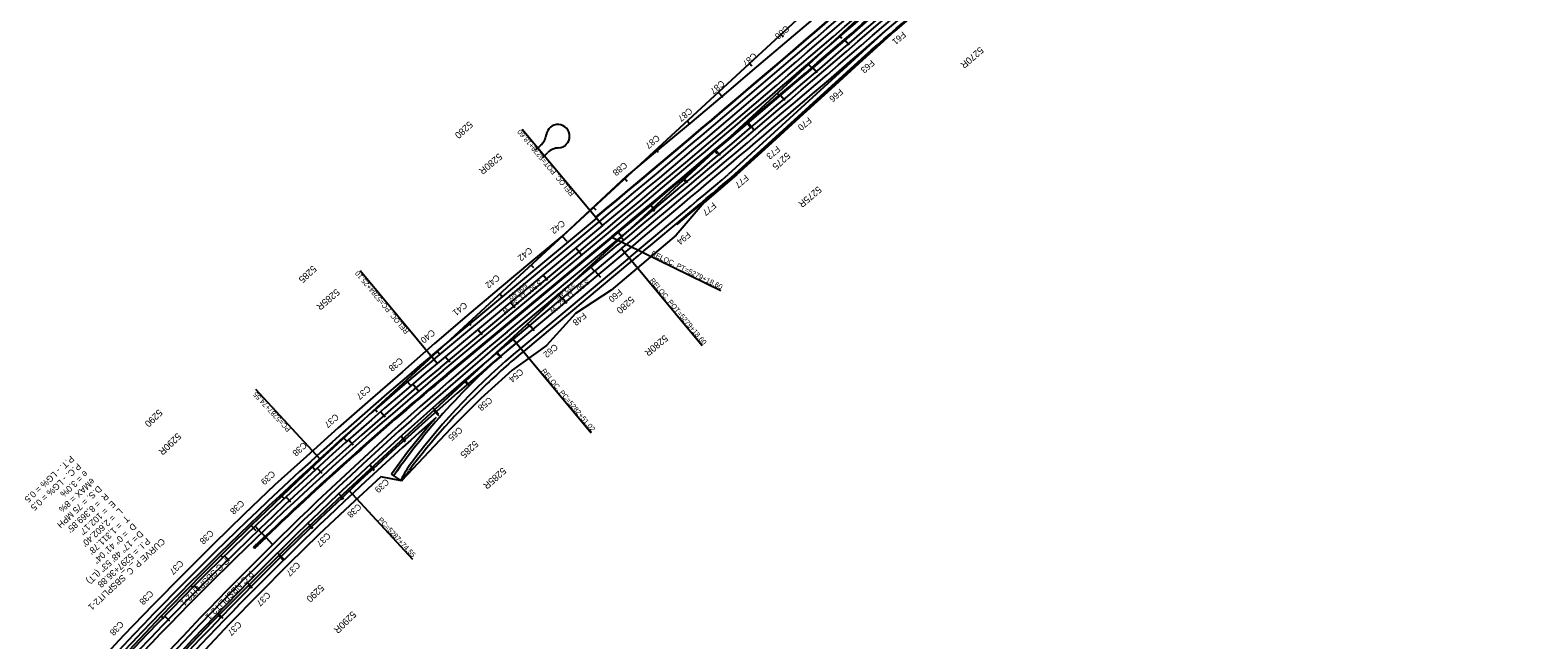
# Model space of a CAD drawing. Extents: x 2160877 to 2175861, y 601747 to 617724.
# Drawn here: x 2162989 to 2166538, y 605470 to 606904 of the extents above; entities that cross this region are included whole.
import ezdxf

# ---------------------------------------------------------------- set-up
doc = ezdxf.new("R2010")
doc.units = 0
for name, color, linetype in [('RD_HC_Cl', 7, 'Continuous'), ('RD_HC_CL_Rel', 7, 'Continuous'), ('RD_HC_Data', 7, 'Continuous'), ('RD_HC_Data_Rel', 7, 'Continuous'), ('RD_HC_Data_Tic', 7, 'Continuous'), ('RD_HC_Data_Tic_Rel', 7, 'Continuous'), ('RD_HC_TX_Rel_Sta50', 7, 'Continuous'), ('RD_HC_TX_Rel_StaOther', 7, 'Continuous'), ('RD_HC_TX_StaOther', 7, 'Continuous'), ('RD_PD_CstnLmt', 7, 'Continuous'), ('RD_PD_CstnLmt_TX', 7, 'Continuous'), ('RD_PD_Final_LnLine', 7, 'Continuous'), ('RD_PD_Final_TrvlWay', 7, 'Continuous'), ('RD_PD_GR', 7, 'Continuous'), ('RD_PD_MedBWall', 7, 'Continuous')]:
    doc.layers.add(name, color=color, linetype=linetype)

msp = doc.modelspace()

# ---------------------------------------------------------------- linework, layer by layer
at = {"layer": 'RD_HC_Cl'}
for p, q in [((2172207.3, 613775.1), (2163672.2, 605893.8)), ((2172272.5, 613704.6), (2163737.4, 605823.3))]:
    msp.add_line(p, q, dxfattribs=at)
for radius in [8641.9, 8545.9]:
    msp.add_arc((2169535, 599544.7), radius, 132.71947, 164.41949, dxfattribs=at)
at = {"layer": 'RD_HC_CL_Rel'}
for p, q in [((2164335.8, 606444.4), (2163946.7, 606120.1)), ((2164380.9, 606390.4), (2164125.5, 606177.5))]:
    msp.add_line(p, q, dxfattribs=at)
for centre, radius, start, end in [((2135996.9, 640448.5), 44300, 309.80773, 312.71947), ((2169810, 599356.6), 8879.1, 129.80773, 145.62858), ((2169305.2, 599690.4), 8369.8, 129.80773, 147.62243)]:
    msp.add_arc(centre, radius, start, end, dxfattribs=at)
at = {"layer": 'RD_HC_Data'}
for p, q in [((2163672.2, 605893.8), (2163520.1, 606058.6)), ((2163737.4, 605823.3), (2163888.4, 605659.7))]:
    msp.add_line(p, q, dxfattribs=at)
at = {"layer": 'RD_HC_Data_Rel'}
for p, q in [((2164335.8, 606444.4), (2164147.1, 606670.9)), ((2164358.3, 606417.4), (2164614.3, 606291.9)), ((2164380.9, 606390.4), (2164570.9, 606162.4)), ((2163946.7, 606120.1), (2163765.3, 606337.8)), ((2164125.5, 606177.5), (2164309.7, 605956.5))]:
    msp.add_line(p, q, dxfattribs=at)
at = {"layer": 'RD_HC_Data_Tic'}
for p, q in [((2164755.6, 606894.2), (2164761, 606888.3)), ((2164894.2, 606891.5), (2164899.6, 606885.6)), ((2164682.1, 606826.3), (2164687.5, 606820.5)), ((2164820.7, 606823.6), (2164826.1, 606817.8)), ((2164608.6, 606758.5), (2164619.5, 606746.7)), ((2164747.2, 606755.8), (2164752.7, 606749.9)), ((2164535.2, 606690.6), (2164540.6, 606684.8)), ((2164673.8, 606688), (2164684.6, 606676.2)), ((2164461.7, 606622.8), (2164467.1, 606616.9)), ((2164600.3, 606620.1), (2164605.7, 606614.2)), ((2164388.2, 606555), (2164393.7, 606549.1)), ((2164526.8, 606552.3), (2164532.3, 606546.4)), ((2164314.8, 606487.1), (2164320.2, 606481.2)), ((2164453.4, 606484.4), (2164458.8, 606478.6)), ((2164241.3, 606419.3), (2164252.1, 606407.5)), ((2164379.9, 606416.6), (2164385.3, 606410.7)), ((2164167.8, 606351.4), (2164173.3, 606345.6)), ((2164306.4, 606348.8), (2164317.3, 606337)), ((2164094.4, 606283.6), (2164099.8, 606277.7)), ((2164233, 606280.9), (2164238.4, 606275)), ((2164020.9, 606215.8), (2164026.3, 606209.9)), ((2164159.5, 606213.1), (2164164.9, 606207.2)), ((2163947.4, 606147.9), (2163952.8, 606142)), ((2164086, 606145.2), (2164091.4, 606139.4)), ((2163873.9, 606080.1), (2163884.8, 606068.3)), ((2164012.5, 606077.4), (2164018, 606071.5)), ((2163800.5, 606012.2), (2163805.9, 606006.4)), ((2163939.1, 606009.5), (2163949.9, 605997.8)), ((2163727, 605944.4), (2163732.4, 605938.5)), ((2163865.6, 605941.7), (2163871, 605935.8)), ((2163653.6, 605876.5), (2163659, 605870.7)), ((2163792.1, 605873.9), (2163797.6, 605868)), ((2163580.7, 605808), (2163586.2, 605802.3)), ((2163718.7, 605806), (2163724.1, 605800.1)), ((2163508.6, 605738.7), (2163519.8, 605727.3)), ((2163645.8, 605737.5), (2163651.3, 605731.7)), ((2163437.4, 605668.6), (2163443, 605662.9)), ((2163573.8, 605668.2), (2163584.9, 605656.7)), ((2163366.9, 605597.6), (2163372.6, 605592)), ((2163502.5, 605598), (2163508.2, 605592.3)), ((2163297.3, 605525.8), (2163303, 605520.3)), ((2163432.1, 605527), (2163437.8, 605521.4))]:
    msp.add_line(p, q, dxfattribs=at)
at = {"layer": 'RD_HC_Data_Tic_Rel'}
for p, q in [((2164906.6, 606881.9), (2164917.1, 606869.8)), ((2164830.8, 606816.7), (2164841.2, 606804.6)), ((2164754.8, 606751.7), (2164765.2, 606739.5)), ((2164678.6, 606686.9), (2164691.6, 606671.6)), ((2164602.4, 606622.2), (2164612.7, 606610)), ((2164525.9, 606557.7), (2164536.2, 606545.5)), ((2164449.3, 606493.4), (2164459.6, 606481.2)), ((2164372.6, 606429.3), (2164382.9, 606417)), ((2164273.3, 606392.3), (2164286.1, 606376.9)), ((2164196.5, 606328.3), (2164206.7, 606316)), ((2164318.3, 606338.2), (2164331.1, 606322.9)), ((2164119.7, 606264.2), (2164129.9, 606251.9)), ((2164241.5, 606274.2), (2164251.7, 606261.9)), ((2164042.8, 606200.2), (2164053.1, 606187.9)), ((2164164.7, 606210.2), (2164174.9, 606197.9)), ((2164087.9, 606146.1), (2164098.3, 606133.8)), ((2163966, 606136.2), (2163976.3, 606123.9)), ((2164011.8, 606081.2), (2164022.3, 606069.1)), ((2163889.4, 606071.9), (2163902.4, 606056.7)), ((2163813.6, 606006.8), (2163824.1, 605994.7)), ((2163936.5, 606015.5), (2163949.7, 606000.5)), ((2163738.5, 605940.7), (2163749.1, 605928.7)), ((2163861.9, 605948.9), (2163872.6, 605937)), ((2163664.2, 605873.7), (2163675, 605861.9)), ((2163788, 605881.5), (2163798.8, 605869.7)), ((2163590.7, 605805.9), (2163601.7, 605794.2)), ((2163714.9, 605813.3), (2163725.9, 605801.6)), ((2163518.1, 605737.2), (2163531.9, 605722.7)), ((2163642.6, 605744.2), (2163653.7, 605732.7)), ((2163446.2, 605667.6), (2163457.4, 605656.2)), ((2163571, 605674.4), (2163585.1, 605660.1)), ((2163375.3, 605597.2), (2163386.6, 605585.9)), ((2163500.3, 605603.7), (2163511.6, 605592.4)), ((2163305.1, 605525.9), (2163316.6, 605514.8)), ((2163430.3, 605532.2), (2163441.8, 605521.1))]:
    msp.add_line(p, q, dxfattribs=at)
at = {"layer": 'RD_PD_CstnLmt'}
for p, q in [((2165098, 606966.6), (2165022.3, 606901)), ((2164851.1, 606946.4), (2164774.7, 606882.1)), ((2165022.3, 606901), (2164948, 606833.8)), ((2164774.7, 606882.1), (2164698.2, 606818)), ((2164948, 606833.8), (2164874, 606766.3)), ((2164698.2, 606818), (2164622.4, 606753.1)), ((2164622.4, 606753.1), (2164546.3, 606688.5)), ((2164874, 606766.3), (2164800, 606698.8)), ((2164546.3, 606688.5), (2164469.6, 606624.7)), ((2164800, 606698.8), (2164725.9, 606631.3)), ((2164469.6, 606624.7), (2164392.9, 606560.8)), ((2164725.9, 606631.3), (2164651.8, 606563.7)), ((2164392.9, 606560.8), (2164246.7, 606424.2)), ((2164651.8, 606563.7), (2164575.6, 606498.7)), ((2164575.6, 606498.7), (2164509.5, 606421.7)), ((2164246.7, 606424.2), (2164169.6, 606360.5)), ((2164509.5, 606421.7), (2164356.5, 606292.4)), ((2164169.6, 606360.5), (2164093, 606296.2)), ((2164418.9, 606344.8), (2164418.9, 606344.8)), ((2164093, 606296.2), (2164016.5, 606231.8)), ((2164356.5, 606292.4), (2164272.2, 606237.3)), ((2164016.5, 606231.8), (2163940.4, 606166.9)), ((2164272.2, 606237.3), (2164204.3, 606162.7)), ((2163940.4, 606166.9), (2163865.1, 606100.5)), ((2164204.3, 606162.7), (2164123, 606104.5)), ((2163865.1, 606100.5), (2163789.3, 606034.7)), ((2164123, 606104.5), (2164049.6, 606037.4)), ((2164049.6, 606037.4), (2163979.3, 605966.9)), ((2163789.3, 606034.7), (2163713.9, 605968.3)), ((2163713.9, 605968.3), (2163638.9, 605901.5)), ((2163979.3, 605966.9), (2163862.6, 605843.8)), ((2163638.9, 605901.5), (2163564.3, 605834.1)), ((2163564.3, 605834.1), (2163491.7, 605764.8)), ((2163814.2, 605853.1), (2163741, 605785.6)), ((2163862.6, 605843.8), (2163814.2, 605853.1)), ((2163491.7, 605764.8), (2163419.9, 605694.5)), ((2163741, 605785.6), (2163668.5, 605717.3)), ((2163419.9, 605694.5), (2163348.9, 605623.5)), ((2163668.5, 605717.3), (2163596.9, 605648.2)), ((2163596.9, 605648.2), (2163526.8, 605577.4)), ((2163348.9, 605623.5), (2163278.1, 605552.2)), ((2163526.8, 605577.4), (2163457.1, 605506.3)), ((2163278.1, 605552.2), (2163208.3, 605480)), ((2163457.1, 605506.3), (2163388.7, 605434)), ((2163208.3, 605480), (2163139.9, 605406.4))]:
    msp.add_line(p, q, dxfattribs=at)
at = {"layer": 'RD_PD_Final_LnLine'}
for p, q in [((2165001.8, 606901.7), (2164631.9, 606564.5)), ((2163939.1, 606129.3), (2164328.1, 606453.6)), ((2163954.4, 606110.9), (2164343.5, 606435.2)), ((2163968.5, 606094), (2164357.6, 606418.3)), ((2163970, 606092.2), (2164359.1, 606416.5)), ((2164117.8, 606186.8), (2164373.2, 606399.6)), ((2164388.5, 606381.1), (2164133.2, 606168.3)), ((2164398.8, 606368.9), (2164143.4, 606156)), ((2163862.6, 605843.8), (2163839.6, 605859.9)), ((2163861.2, 605844.7), (2163861.9, 605846.1)), ((2163543.1, 605711), (2163533.3, 605721.3)), ((2163543.1, 605711), (2163559.5, 605693.9))]:
    msp.add_line(p, q, dxfattribs=at)
for centre, radius, start, end in [((2135996.9, 640448.5), 44252.8, 309.80773, 312.71947), ((2135996.9, 640448.5), 44264.8, 309.80773, 312.71947), ((2135996.9, 640448.5), 44276.8, 309.80773, 312.71947), ((2135996.9, 640448.5), 44298.8, 309.80773, 312.71947), ((2135996.9, 640448.5), 44301.2, 309.80773, 312.71947), ((2135996.9, 640448.5), 44323.2, 309.80773, 312.71947), ((2135996.9, 640448.5), 44335.2, 309.80773, 312.71947), ((2135996.9, 640448.5), 44347.2, 310.84704, 312.71947), ((2135996.9, 640448.5), 44239.7, 309.80773, 311.15408), ((2135996.9, 640448.5), 44240.8, 309.80773, 311.15408), ((2135996.9, 640448.5), 44347.2, 309.80773, 310.84704), ((2135996.9, 640448.5), 44363.2, 309.80773, 310.20085), ((2169810, 599356.6), 8891.1, 129.80773, 145.62858), ((2169810, 599356.6), 8867.1, 129.80773, 144.89859), ((2165149.7, 604937.9), 1596, 129.5633, 144.8644), ((2165161.7, 604927.1), 1596, 129.6453, 143.0585), ((2169305.2, 599690.4), 8357.8, 129.80773, 147.62243), ((2169305.2, 599690.4), 8381.8, 129.80773, 136.90521), ((2169327, 599664.3), 8369.8, 129.80773, 133.72726), ((2169327, 599664.3), 8367.5, 129.80773, 133.72726), ((2164070.6, 605747.6), 230.8, 143.0585, 154.736)]:
    msp.add_arc(centre, radius, start, end, dxfattribs=at)
at = {"layer": 'RD_PD_Final_TrvlWay'}
for p, q in [((2164954.1, 606844.7), (2164638.5, 606557)), ((2164954.8, 606843.8), (2164639.3, 606556.2)), ((2164178, 606621.8), (2164191.1, 606633.9)), ((2164194.4, 606604.9), (2164207.2, 606616.7)), ((2163932.7, 606137), (2164321.7, 606461.3)), ((2164321.7, 606461.3), (2164320.5, 606462.8)), ((2163960.8, 606103.2), (2164349.9, 606427.5)), ((2164111.4, 606194.4), (2164366.8, 606407.3)), ((2164405.2, 606361.2), (2164149.8, 606148.4)), ((2163862.6, 605843.8), (2163880.5, 605867.8))]:
    msp.add_line(p, q, dxfattribs=at)
for centre, radius, start, end in [((2135996.9, 640448.5), 44286.8, 309.80773, 311.17861), ((2135996.9, 640448.5), 44313.2, 309.80773, 311.17861), ((2136000.8, 640444), 44353.2, 310.7522, 311.15415), ((2136000.8, 640444), 44354.3, 310.75222, 311.15415), ((2164231, 606654.8), 27.5, 272.8804, 172.6984), ((2164164, 606663.3), 40, 312.7195, 352.6984), ((2164234.4, 606587.3), 40, 92.8804, 132.7195), ((2135996.9, 640448.5), 44373.2, 309.80773, 310.2011), ((2135996.9, 640448.5), 44374.3, 309.98432, 310.20112), ((2169810, 599356.6), 8901.1, 129.80773, 142.13894), ((2165161.7, 604927.1), 1586, 129.6453, 134.0776), ((2169305.2, 599690.4), 8391.8, 129.80773, 137.30123), ((2169305.2, 599690.4), 8347.8, 129.80773, 143.57306), ((2165082.4, 604970.4), 1500, 133.0506, 143.2516), ((2169810, 599356.6), 8857.1, 131.47407, 142.45996), ((2165149.7, 604937.9), 1602, 138.8128, 144.8644)]:
    msp.add_arc(centre, radius, start, end, dxfattribs=at)
at = {"layer": 'RD_PD_GR'}
for p, q in [((2163541.1, 605713.2), (2163514.4, 605687.5)), ((2163514.4, 605687.5), (2163514.7, 605687.2)), ((2163514.7, 605687.2), (2163541.4, 605712.8)), ((2163515.4, 605688.6), (2163516.7, 605689.8)), ((2163515.8, 605688.2), (2163517.1, 605689.4)), ((2163517.2, 605686.7), (2163515.8, 605688.2)), ((2163516.9, 605688.3), (2163516, 605689.2)), ((2163517.5, 605688.9), (2163516.3, 605687.7)), ((2163516.3, 605687.7), (2163517.7, 605686.3)), ((2163516.6, 605685.2), (2163543.3, 605710.9)), ((2163516.9, 605684.9), (2163516.6, 605685.2)), ((2163543.6, 605710.5), (2163516.9, 605684.9)), ((2163517.1, 605689.4), (2163518.5, 605688)), ((2163518.5, 605688), (2163517.2, 605686.7)), ((2163518.9, 605687.5), (2163517.5, 605688.9)), ((2163517.7, 605686.3), (2163518.9, 605687.5)), ((2163517.8, 605687.4), (2163518.7, 605686.5)), ((2163518.1, 605685.8), (2163519.3, 605687.1)), ((2163519.3, 605691.6), (2163519, 605691.9)), ((2163521.2, 605694.2), (2163522.4, 605695.4)), ((2163521.2, 605689.6), (2163521.5, 605689.3)), ((2163521.6, 605693.7), (2163522.8, 605694.9)), ((2163523, 605692.3), (2163521.6, 605693.7)), ((2163522.7, 605693.9), (2163521.8, 605694.8)), ((2163523.3, 605694.5), (2163522, 605693.3)), ((2163522, 605693.3), (2163523.4, 605691.8)), ((2163522.8, 605694.9), (2163524.2, 605693.5)), ((2163524.2, 605693.5), (2163523, 605692.3)), ((2163524.7, 605693), (2163523.3, 605694.5)), ((2163523.4, 605691.8), (2163524.7, 605693)), ((2163523.6, 605692.9), (2163524.5, 605692)), ((2163523.8, 605691.4), (2163525.1, 605692.6)), ((2163526.9, 605699.7), (2163528.2, 605700.9)), ((2163527.3, 605699.3), (2163528.6, 605700.5)), ((2163528.7, 605697.8), (2163527.3, 605699.3)), ((2163528.4, 605699.4), (2163527.6, 605700.3)), ((2163529.1, 605700), (2163527.8, 605698.8)), ((2163527.8, 605698.8), (2163529.2, 605697.4)), ((2163528.6, 605700.5), (2163530, 605699.1)), ((2163530, 605699.1), (2163528.7, 605697.8)), ((2163530.5, 605698.6), (2163529.1, 605700)), ((2163529.2, 605697.4), (2163530.5, 605698.6)), ((2163529.4, 605698.4), (2163530.2, 605697.5)), ((2163529.6, 605696.9), (2163530.9, 605698.2)), ((2163532.7, 605705.2), (2163534, 605706.5)), ((2163533.1, 605704.8), (2163534.4, 605706)), ((2163534.5, 605703.4), (2163533.1, 605704.8)), ((2163534.2, 605705), (2163533.3, 605705.9)), ((2163534.8, 605705.6), (2163533.6, 605704.3)), ((2163533.6, 605704.3), (2163535, 605702.9)), ((2163534.4, 605706), (2163535.8, 605704.6)), ((2163535.8, 605704.6), (2163534.5, 605703.4)), ((2163536.2, 605704.1), (2163534.8, 605705.6)), ((2163535, 605702.9), (2163536.2, 605704.1)), ((2163535.1, 605704), (2163536, 605703.1)), ((2163535.4, 605702.5), (2163536.6, 605703.7)), ((2163538.5, 605710.8), (2163539.7, 605712)), ((2163538.9, 605710.4), (2163540.1, 605711.6)), ((2163540.3, 605708.9), (2163538.9, 605710.4)), ((2163540, 605710.5), (2163539.1, 605711.4)), ((2163540.6, 605711.1), (2163539.3, 605709.9)), ((2163539.3, 605709.9), (2163540.7, 605708.5)), ((2163540.1, 605711.6), (2163541.5, 605710.1)), ((2163541.5, 605710.1), (2163540.3, 605708.9)), ((2163542, 605709.7), (2163540.6, 605711.1)), ((2163540.7, 605708.5), (2163542, 605709.7)), ((2163540.9, 605709.5), (2163541.8, 605708.6)), ((2163541.4, 605712.8), (2163541.1, 605713.2)), ((2163541.1, 605708), (2163542.4, 605709.2)), ((2163543.3, 605710.9), (2163543.6, 605710.5))]:
    msp.add_line(p, q, dxfattribs=at)
at = {"layer": 'RD_PD_MedBWall'}
for p, q in [((2164955.5, 606843), (2164640, 606555.4)), ((2164511.5, 606447.2), (2164510.1, 606448.9))]:
    msp.add_line(p, q, dxfattribs=at)
for centre, radius, start, end in [((2136000.8, 640444), 44355.4, 310.75224, 311.15415), ((2135996.9, 640448.5), 44375.4, 309.98432, 310.2012)]:
    msp.add_arc(centre, radius, start, end, dxfattribs=at)

# ---------------------------------------------------------------- texts
at = {"layer": 'RD_HC_Data'}
for rotation, p in [(132.7195, (2163602.9, 605965.9)), (312.7195, (2163806.7, 605751.2))]:
    msp.add_text('PC=5287+74.55', height=12, rotation=rotation, dxfattribs=at).set_placement(p)
at = {"layer": 'RD_HC_Data_Rel'}
for s, height, rotation, p in [('RELOC. POT=5279+18.60', 12, 129.8077, (2164270.3, 606519.9)), ('RELOC. PT=5279+18.60', 12, 333.8917, (2164449, 606375.2)), ('RELOC. PC=5284+25.10', 12, 129.8077, (2163881.2, 606195.7)), ('RELOC. POT=5279+18.60', 12, 309.8077, (2164446.4, 606314.8)), ('RELOC. PC=5282+51.02', 12, 309.8077, (2164191, 606102)), ('P.T. - LG% = 0.5', 15, 222.7195, (2163083.9, 605904.2)), ('P.C. - LG% = 0.5', 15, 222.7195, (2163100.2, 605886.6)), ('e = 3.0%', 15, 222.7195, (2163116.5, 605869)), ('D.S. = 75 MPH', 15, 222.7195, (2163149, 605833.7)), ('eMAX = 8%', 15, 222.7195, (2163132.7, 605851.3)), ("R  = 8,369.85'", 15, 222.7195, (2163165.3, 605816.1)), ("E  = 102.17'", 15, 222.7195, (2163181.6, 605798.4)), ("L  = 2,602.40'", 15, 222.7195, (2163197.9, 605780.8)), ("T  = 1,311.78'", 15, 222.7195, (2163214.1, 605763.2)), ('D  = 0%%d 41\' 04"', 15, 222.7195, (2163230.4, 605745.5)), ('D ', 15, 222.7195, (2163246.7, 605727.9)), ('   = 17%%d 48\' 53" (LT)', 15, 222.7195, (2163246.7, 605727.9)), ('CURVE P_C_SBSPLIT2-1', 15, 222.7195, (2163298, 605710)), ('P.I. = 5297+36.88', 15, 222.7195, (2163263, 605710.3)), ('P C SBSPLIT2-1', 15, 224.5304, (2163448.1, 605663.6)), ('P C NBSPLIT2-1', 15, 225.4895, (2163506.1, 605633.9))]:
    msp.add_text(s, height=height, rotation=rotation, dxfattribs=at).set_placement(p)
at = {"layer": 'RD_HC_TX_Rel_Sta50'}
for s, rotation, p in [('5270R', 220.9958, (2165224.6, 606866.2)), ('5280R', 219.8077, (2164091.9, 606616)), ('5275R', 220.3491, (2164843.5, 606538.3)), ('5285R', 220.3205, (2163709.1, 606296.9)), ('5280R', 219.8077, (2164482, 606188.3)), ('5290R', 223.7432, (2163335, 605957.8)), ('5285R', 221.4144, (2164100.7, 605876.4)), ('5290R', 224.6408, (2163746.8, 605538.7))]:
    msp.add_text(s, height=16, rotation=rotation, dxfattribs=at).set_placement(p)
at = {"layer": 'RD_HC_TX_Rel_StaOther'}
for s, p in [('S 50%%d 11\' 32" W', (2164188.2, 606317.5)), ("506.50'", (2164152.3, 606311)), ('S 50%%d 11\' 32" W', (2164300.1, 606319.2)), ("332.42'", (2164264.2, 606312.7))]:
    msp.add_text(s, height=12, rotation=219.8077, dxfattribs=at).set_placement(p)
at = {"layer": 'RD_HC_TX_StaOther'}
for s, rotation, p in [('5280', 222.7195, (2164021.8, 606691.4)), ('5275', 222.7195, (2164769.2, 606618.2)), ('5285', 222.7195, (2163654.1, 606351.9)), ('5280', 222.7195, (2164402.3, 606279.4)), ('5290', 224.2142, (2163290.9, 606013.4)), ('5285', 222.7195, (2164034.6, 605939.8)), ('5290', 224.231, (2163671.4, 605601.3))]:
    msp.add_text(s, height=16, rotation=rotation, dxfattribs=at).set_placement(p)
at = {"layer": 'RD_PD_CstnLmt_TX'}
for s, rotation, p in [('C86', 220.6078, (2164768.2, 606916.6)), ('F61', 220.8665, (2165042.4, 606902.3)), ('C87', 220.4785, (2164691.8, 606852.4)), ('F63', 220.7371, (2164968.7, 606835.6)), ('C87', 220.3491, (2164615.9, 606787.6)), ('F66', 220.6078, (2164894.6, 606767.9)), ('C87', 220.2198, (2164539.9, 606723)), ('F70', 220.4785, (2164820.6, 606700.5)), ('C87', 220.0905, (2164463.2, 606659.1)), ('F73', 220.3491, (2164746.6, 606632.9)), ('C88', 219.9611, (2164386.7, 606595.2)), ('F77', 220.2198, (2164672.4, 606565.2)), ('F77', 220.0905, (2164596.2, 606500.2)), ('C42', 219.8077, (2164240.3, 606458.5)), ('F94', 219.9611, (2164535.9, 606431.4)), ('C42', 219.8077, (2164163.3, 606394.7)), ('C42', 219.8077, (2164086.6, 606330.5)), ('F60', 219.8077, (2164375, 606296.4)), ('C41', 219.8077, (2164009.9, 606265.8)), ('F48', 219.8077, (2164290.7, 606241.3)), ('C40', 219.8077, (2163934.3, 606201.3)), ('C62', 219.8077, (2164223.4, 606167.2)), ('C38', 220.3205, (2163858.8, 606135.1)), ('C54', 220.1238, (2164142.1, 606109.1)), ('C37', 221.005, (2163782.6, 606069.2)), ('C58', 220.7691, (2164068.9, 606042.4)), ('C37', 221.6896, (2163707, 606002.9)), ('C65', 221.4144, (2163998.6, 605972.2)), ('C38', 222.3741, (2163631.8, 605936.3)), ('C39', 223.0587, (2163557.1, 605869)), ('C39', 222.705, (2163825.3, 605850)), ('C38', 223.7432, (2163484.2, 605799.7)), ('C38', 223.3502, (2163760.1, 605791.5)), ('C38', 224.4278, (2163412.1, 605729.6)), ('C37', 223.9955, (2163687.4, 605723.4)), ('C37', 225.1123, (2163340.8, 605658.5)), ('C37', 224.6408, (2163615.7, 605654.5)), ('C38', 225.7969, (2163269.8, 605587.4)), ('C37', 225.2861, (2163545.6, 605583.9)), ('C38', 226.4814, (2163199.8, 605515.2)), ('C37', 225.9314, (2163477.4, 605514.6))]:
    msp.add_text(s, height=15, rotation=rotation, dxfattribs=at).set_placement(p)

doc.saveas('drawing.dxf')
